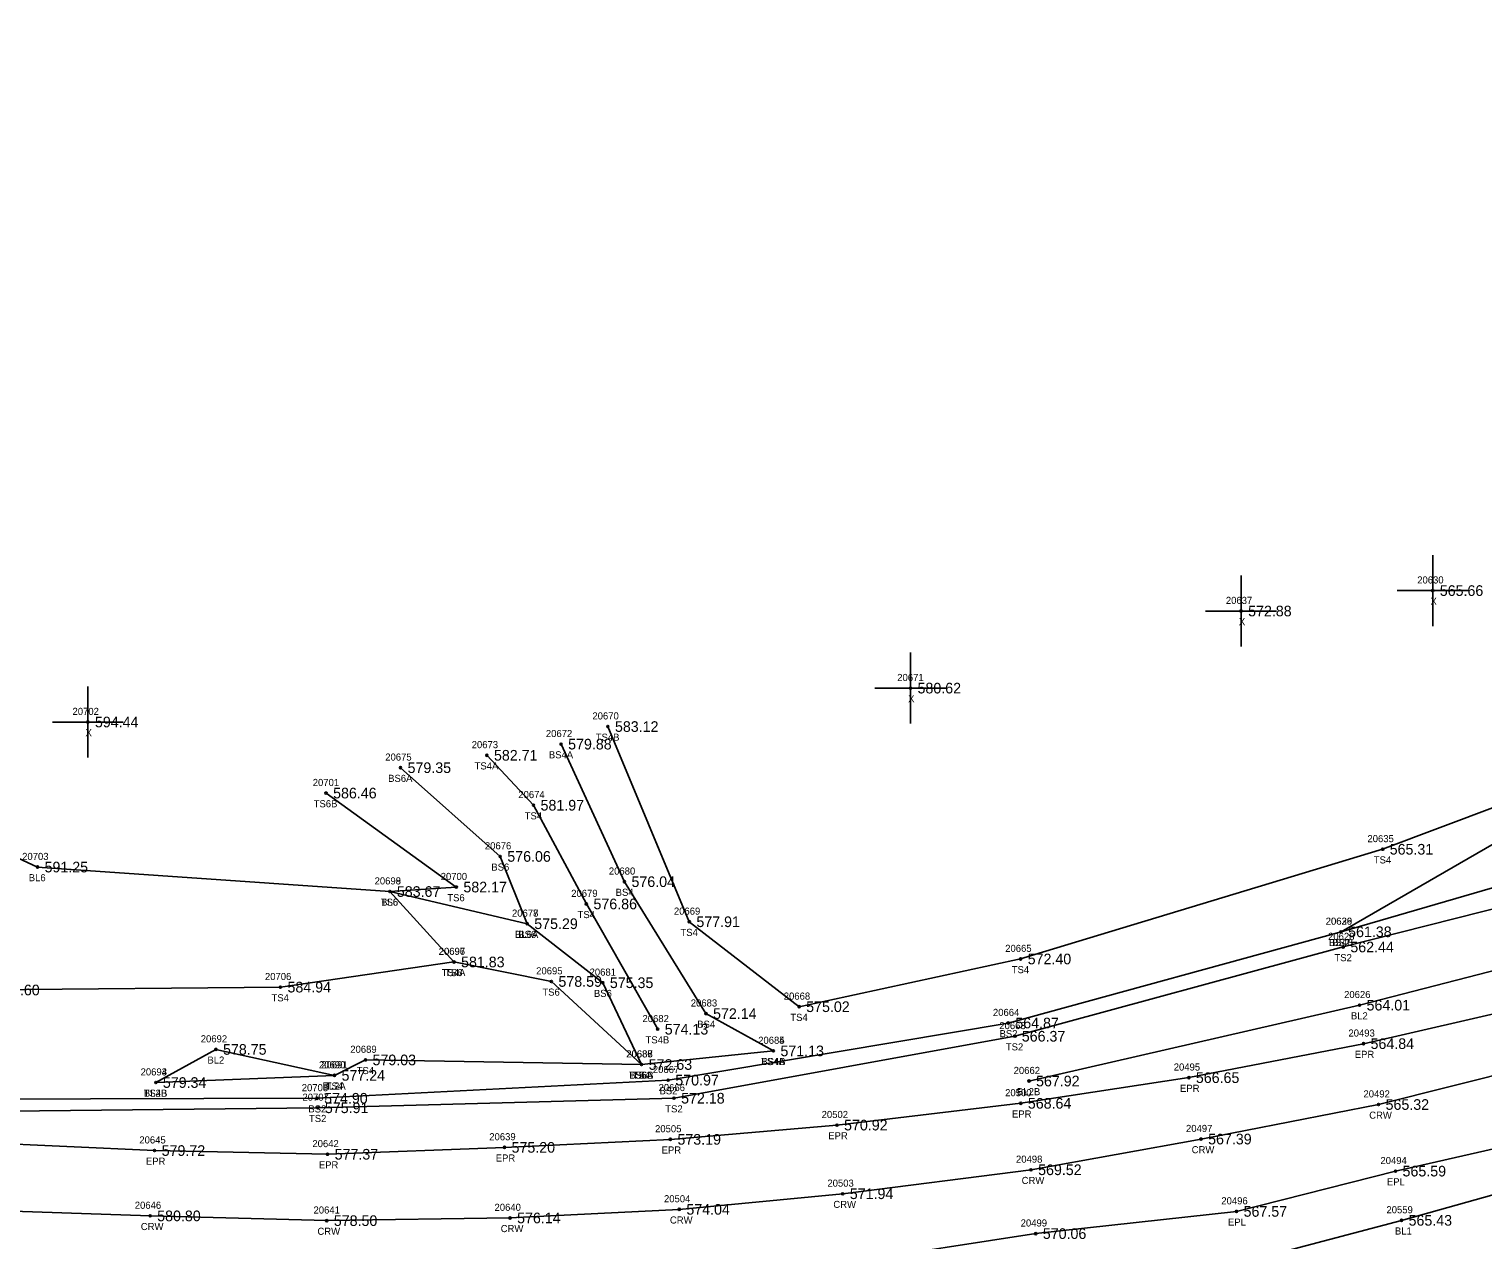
# Model space of a CAD drawing. Extents: x 1540443 to 1541844, y 887157 to 888162.
# Drawn here: x 1540572.9 to 1540777.9, y 887551.3 to 887722 of the extents above; entities that cross this region are included whole.
import ezdxf

# ---------------------------------------------------------------- set-up
doc = ezdxf.new("R2010")
doc.units = 0
for name, color, linetype in [('RD_DTM_BkLn1', 7, 'Continuous'), ('RD_DTM_BkLn2', 7, 'Continuous'), ('RD_DTM_BkLn_txCode', 7, 'Continuous'), ('RD_EX_Misc', 7, 'Continuous'), ('RD_EX_Misc_txCode', 7, 'Continuous'), ('RD_EX_Road', 7, 'Continuous'), ('RD_EX_Road_txCode', 7, 'Continuous'), ('RD_EX_TX_Misc_ELEV', 7, 'Continuous'), ('RD_EX_TX_Road_ELEV', 7, 'Continuous'), ('RD_HC_Survey_ELEV', 7, 'Continuous'), ('RD_HC_Survey_txCode', 7, 'Continuous'), ('RD_SMD_Locator', 7, 'Continuous')]:
    doc.layers.add(name, color=color, linetype=linetype)

msp = doc.modelspace()

# ---------------------------------------------------------------- linework, layer by layer
at = {"layer": 'RD_DTM_BkLn1'}
for points in [[(1541121.11, 887687.12), (1541102.24, 887681.39), (1541047.23, 887667.07), (1540999.54, 887652.68), (1540951.37, 887639.83), (1540901.44, 887627.14), (1540855.78, 887612.94), (1540807.53, 887596.54), (1540760.49, 887584.4), (1540713.89, 887573.7)], [(1541126.44, 887673.83), (1541099.94, 887665.81), (1541052.06, 887651.29), (1541003.93, 887637.63), (1540955.85, 887623.48), (1540907.97, 887609.13), (1540859.88, 887595.48), (1540836.31, 887588.86), (1540811.54, 887582.34), (1540783.96, 887575.59), (1540763.17, 887570.39), (1540738.15, 887565.52), (1540714.18, 887561.19), (1540687.63, 887557.81), (1540664.59, 887555.61), (1540640.72, 887554.4), (1540614.88, 887554.02), (1540589.98, 887554.69), (1540565.01, 887555.56), (1540543.6, 887557.4), (1540515.55, 887560.7), (1540490.9, 887564.25), (1540466.38, 887568.75)], [(1540643.14, 887595.88), (1540623.77, 887600.42), (1540574.1, 887603.87), (1540547.73, 887616.11)], [(1540954.63, 887607.67), (1540911.91, 887595.52), (1540863.1, 887582.06), (1540814.48, 887567.51), (1540766.41, 887554.06), (1540717.46, 887541.1), (1540667.62, 887534.76)], [(1540615.97, 887574.5), (1540599.26, 887578.16), (1540590.78, 887573.49)]]:
    msp.add_lwpolyline(points, dxfattribs=at)
at = {"layer": 'RD_DTM_BkLn2'}
for points in [[(1540916.4, 887722.02), (1540881.96, 887690.29), (1540835.96, 887661.52), (1540805.74, 887626.62), (1540783.69, 887609.62), (1540757.89, 887594.74)], [(1541125.73, 887711), (1541094.52, 887702.99), (1541086.54, 887695.93), (1541048.87, 887683.66), (1540995.75, 887663.85), (1540948.75, 887649.66), (1540899.3, 887637.78), (1540852.09, 887622.25), (1540804.6, 887608.33), (1540757.89, 887594.74), (1540710.97, 887581.88), (1540663.03, 887573.83), (1540613.52, 887571.27), (1540565.55, 887571.13), (1540516.75, 887576.29), (1540467.77, 887583.94)], [(1541121.11, 887687.12), (1541116.34, 887691.41), (1541100.71, 887685.78), (1541045.17, 887674.13), (1540997.29, 887658.19), (1540949.92, 887645.1), (1540900.33, 887634.17), (1540852.81, 887620.54), (1540805.55, 887604.61), (1540758.2, 887592.6), (1540711.88, 887580.02), (1540663.85, 887571.28), (1540613.62, 887569.93), (1540565.66, 887569.42), (1540516.87, 887574.64), (1540467.8, 887581.76)], [(1540787.05, 887622.79), (1540780, 887612.51), (1540763.75, 887606.38), (1540712.71, 887590.91), (1540681.48, 887584.18), (1540666, 887596.16), (1540654.52, 887623.68)], [(1540647.92, 887621.2), (1540656.85, 887601.81), (1540668.35, 887583.21), (1540677.85, 887577.95)], [(1540637.46, 887619.63), (1540644.03, 887612.59), (1540651.49, 887598.67), (1540661.54, 887581.01)], [(1540625.28, 887617.88), (1540639.34, 887605.37), (1540643.14, 887595.88), (1540653.8, 887587.56), (1540659.27, 887576.03)], [(1540659.27, 887576.03), (1540646.55, 887587.74), (1540632.82, 887590.49), (1540623.77, 887600.42), (1540633.15, 887601.05), (1540614.78, 887614.3)], [(1540632.82, 887590.49), (1540608.35, 887586.94), (1540567.28, 887586.54), (1540523.85, 887592.4), (1540472.43, 887598.18)], [(1540677.85, 887577.95), (1540659.27, 887576.03), (1540620.34, 887576.68), (1540615.97, 887574.5), (1540590.78, 887573.49)]]:
    msp.add_lwpolyline(points, dxfattribs=at)
at = {"layer": 'RD_EX_Misc'}
for p, q in [((1540770.81, 887637.85), (1540770.81, 887647.85)), ((1540743.79, 887634.97), (1540743.79, 887644.97)), ((1540765.81, 887642.85), (1540775.81, 887642.85)), ((1540738.79, 887639.97), (1540748.79, 887639.97)), ((1540697.18, 887624.1), (1540697.18, 887634.1)), ((1540581.2, 887619.32), (1540581.2, 887629.32)), ((1540692.18, 887629.1), (1540702.18, 887629.1)), ((1540576.2, 887624.32), (1540586.2, 887624.32))]:
    msp.add_line(p, q, dxfattribs=at)
at = {"layer": 'RD_EX_Road'}
for points in [[(1541123.73, 887682.83), (1541097.11, 887675.72), (1541048.24, 887661.15), (1541001.64, 887647.51), (1540952.42, 887633.12), (1540904.06, 887618.5), (1540857.24, 887604.78), (1540833.63, 887598.38), (1540808.59, 887591.31), (1540783.7, 887584.16), (1540761.05, 887578.97), (1540736.42, 887574.18), (1540712.73, 887570.56), (1540686.82, 887567.49), (1540663.33, 887565.48), (1540639.94, 887564.35), (1540615, 887563.38), (1540590.61, 887563.9), (1540565.81, 887565.05), (1540541.4, 887567.22), (1540516.92, 887569.69), (1540492.5, 887573.72), (1540467.49, 887577.97)], [(1541128.99, 887664.81), (1541102.04, 887656.79), (1541055.37, 887642.78), (1541004.6, 887628.06), (1540958.93, 887614.62), (1540910.77, 887599.96), (1540863.12, 887586.35), (1540837, 887578.35), (1540814.37, 887572.63), (1540785.6, 887565.57), (1540765.56, 887561), (1540743.15, 887555.32), (1540714.84, 887552.19), (1540688.66, 887548.15), (1540665.15, 887545.04), (1540640.91, 887544.2), (1540614.99, 887544.1), (1540590.77, 887544.52), (1540565.35, 887545.64), (1540542.9, 887547.56), (1540513.68, 887550.75), (1540490.5, 887554.02), (1540464.65, 887559.04)]]:
    msp.add_lwpolyline(points, dxfattribs=at)
at = {"layer": 'RD_SMD_Locator'}
for centre in [(1540770.81, 887642.85), (1540743.79, 887639.97), (1540697.18, 887629.1), (1540581.2, 887624.32), (1540654.52, 887623.68), (1540647.92, 887621.2), (1540637.46, 887619.63), (1540625.28, 887617.88), (1540614.78, 887614.3), (1540644.03, 887612.59), (1540763.75, 887606.38), (1540639.34, 887605.37), (1540574.1, 887603.87), (1540623.77, 887600.42), (1540623.77, 887600.42), (1540633.15, 887601.05), (1540656.85, 887601.81), (1540651.49, 887598.67), (1540666, 887596.16), (1540643.14, 887595.88), (1540643.14, 887595.88), (1540757.89, 887594.74), (1540757.89, 887594.74), (1540758.2, 887592.6), (1540632.82, 887590.49), (1540632.82, 887590.49), (1540712.71, 887590.91), (1540608.35, 887586.94), (1540646.55, 887587.74), (1540653.8, 887587.56), (1540681.48, 887584.18), (1540760.49, 887584.4), (1540668.35, 887583.21), (1540710.97, 887581.88), (1540661.54, 887581.01), (1540711.88, 887580.02), (1540599.26, 887578.16), (1540677.85, 887577.95), (1540677.85, 887577.95), (1540761.05, 887578.97), (1540620.34, 887576.68), (1540659.27, 887576.03), (1540659.27, 887576.03), (1540659.27, 887576.03), (1540615.97, 887574.5), (1540615.97, 887574.5), (1540663.03, 887573.83), (1540713.89, 887573.7), (1540736.42, 887574.18), (1540590.78, 887573.49), (1540590.78, 887573.49), (1540613.52, 887571.27), (1540613.62, 887569.93), (1540663.85, 887571.28), (1540712.73, 887570.56), (1540763.17, 887570.39), (1540686.82, 887567.49), (1540663.33, 887565.48), (1540738.15, 887565.52), (1540590.61, 887563.9), (1540615, 887563.38), (1540639.94, 887564.35), (1540714.18, 887561.19), (1540765.56, 887561), (1540687.63, 887557.81), (1540664.59, 887555.61), (1540743.15, 887555.32), (1540589.98, 887554.69), (1540614.88, 887554.02), (1540640.72, 887554.4), (1540766.41, 887554.06), (1540714.84, 887552.19)]:
    msp.add_circle(centre, 0.15, dxfattribs=at)

# ---------------------------------------------------------------- texts
at = {"layer": 'RD_DTM_BkLn_txCode'}
for s, p in [('20670', (1540652.34, 887624.68)), ('20672', (1540645.78, 887622.2)), ('20673', (1540635.32, 887620.63)), ('TS4B', (1540652.81, 887621.68)), ('20675', (1540623.13, 887618.88)), ('BS4A', (1540646.2, 887619.2)), ('BS6A', (1540623.54, 887615.88)), ('TS4A', (1540635.73, 887617.63)), ('20701', (1540612.91, 887615.3)), ('TS6B', (1540613.04, 887612.3)), ('20674', (1540641.89, 887613.59)), ('TS4', (1540642.79, 887610.59)), ('20676', (1540637.18, 887606.37)), ('20635', (1540761.61, 887607.38)), ('20703', (1540571.94, 887604.87)), ('TS4', (1540762.51, 887604.38)), ('BL6', (1540572.87, 887601.87)), ('20698', (1540621.63, 887601.42)), ('20699', (1540621.63, 887601.42)), ('20700', (1540630.95, 887602.05)), ('BS6', (1540638.09, 887603.37)), ('20680', (1540654.66, 887602.81)), ('20679', (1540649.35, 887599.67)), ('BS4', (1540655.62, 887599.81)), ('TS6', (1540622.51, 887598.42)), ('BL6', (1540622.55, 887598.42)), ('TS6', (1540631.88, 887599.05)), ('20677', (1540641, 887596.88)), ('20678', (1540641, 887596.88)), ('TS4', (1540650.25, 887596.67)), ('20669', (1540663.83, 887597.16)), ('20636', (1540755.72, 887595.74)), ('20629', (1540755.74, 887595.74)), ('BL6A', (1540641.43, 887593.88)), ('BS6', (1540641.89, 887593.88)), ('TS4', (1540664.75, 887594.16)), ('20628', (1540756.06, 887593.6)), ('20696', (1540630.66, 887591.49)), ('20697', (1540630.68, 887591.49)), ('20665', (1540710.54, 887591.91)), ('BS4B', (1540756.19, 887592.74)), ('BS2', (1540756.66, 887592.74)), ('TS2', (1540756.96, 887590.6)), ('20706', (1540606.17, 887587.94)), ('TS4A', (1540631.09, 887588.49)), ('TS6', (1540631.56, 887588.49)), ('20695', (1540644.41, 887588.74)), ('20681', (1540651.94, 887588.56)), ('TS4', (1540711.46, 887588.91)), ('TS6', (1540645.29, 887585.74)), ('BS6', (1540652.55, 887585.56)), ('20668', (1540679.32, 887585.18)), ('20626', (1540758.32, 887585.4)), ('TS4', (1540607.1, 887584.94)), ('20683', (1540666.21, 887584.21)), ('20682', (1540659.4, 887582.01)), ('BS4', (1540667.12, 887581.21)), ('TS4', (1540680.24, 887582.18)), ('20664', (1540708.81, 887582.88)), ('20663', (1540709.71, 887581.02)), ('BL2', (1540759.28, 887582.4)), ('20692', (1540597.12, 887579.16)), ('TS4B', (1540659.83, 887579.01)), ('20684', (1540675.71, 887578.95)), ('20685', (1540675.71, 887578.95)), ('BS2', (1540709.74, 887579.88)), ('20689', (1540618.2, 887577.68)), ('20686', (1540657.1, 887577.03)), ('20687', (1540657.13, 887577.03)), ('20688', (1540657.13, 887577.03)), ('TS2', (1540710.63, 887578.02)), ('BL2', (1540598.06, 887576.16)), ('20690', (1540613.79, 887575.5)), ('20691', (1540614.11, 887575.5)), ('20667', (1540660.86, 887574.83)), ('TS4A', (1540676.12, 887575.95)), ('BS4B', (1540676.15, 887575.95)), ('20693', (1540588.64, 887574.49)), ('20694', (1540588.64, 887574.49)), ('TS4', (1540619.1, 887574.68)), ('TS6A', (1540657.51, 887574.03)), ('BS6B', (1540657.54, 887574.03)), ('TS4', (1540658.02, 887574.03)), ('20662', (1540711.73, 887574.7)), ('TS4B', (1540589.07, 887571.49)), ('BL2B', (1540589.1, 887571.49)), ('20708', (1540611.36, 887572.27)), ('20707', (1540611.46, 887570.93)), ('BL2A', (1540614.28, 887572.5)), ('TS4', (1540614.73, 887572.5)), ('20666', (1540661.67, 887572.28)), ('BS2', (1540661.8, 887571.83)), ('BL2B', (1540712.21, 887571.7)), ('BS2', (1540612.29, 887569.27)), ('TS2', (1540662.61, 887569.28)), ('TS2', (1540612.38, 887567.93)), ('20559', (1540764.29, 887555.06)), ('BL1', (1540765.49, 887552.06))]:
    msp.add_text(s, height=1, dxfattribs=at).set_placement(p)
at = {"layer": 'RD_EX_Misc_txCode'}
for s, p in [('20630', (1540768.63, 887643.85)), ('20637', (1540741.65, 887640.97)), ('X', (1540770.5, 887640.85)), ('X', (1540743.48, 887637.97)), ('20671', (1540695.32, 887630.1)), ('X', (1540696.86, 887627.1)), ('20702', (1540579.04, 887625.32)), ('X', (1540580.88, 887622.32))]:
    msp.add_text(s, height=1, dxfattribs=at).set_placement(p)
at = {"layer": 'RD_EX_Road_txCode'}
for s, p in [('20493', (1540758.93, 887579.97)), ('EPR', (1540759.82, 887576.97)), ('20495', (1540734.3, 887575.18)), ('20500', (1540710.53, 887571.56)), ('EPR', (1540735.19, 887572.18)), ('20502', (1540684.66, 887568.49)), ('EPR', (1540711.5, 887568.56)), ('20645', (1540588.46, 887564.9)), ('20639', (1540637.8, 887565.35)), ('20505', (1540661.17, 887566.48)), ('EPR', (1540685.59, 887565.49)), ('20642', (1540612.86, 887564.38)), ('EPR', (1540662.1, 887563.48)), ('EPR', (1540589.38, 887561.9)), ('EPR', (1540613.77, 887561.38)), ('EPR', (1540638.71, 887562.35)), ('20494', (1540763.44, 887562)), ('EPL', (1540764.35, 887559)), ('20496', (1540741.01, 887556.32)), ('20499', (1540712.72, 887553.19)), ('EPL', (1540741.95, 887553.32))]:
    msp.add_text(s, height=1, dxfattribs=at).set_placement(p)
at = {"layer": 'RD_EX_TX_Misc_ELEV'}
for s, p in [('565.66', (1540771.81, 887642.1)), ('572.88', (1540744.79, 887639.22)), ('580.62', (1540698.18, 887628.35)), ('594.44', (1540582.2, 887623.57)), ('583.12', (1540655.52, 887622.93)), ('579.88', (1540648.92, 887620.45)), ('582.71', (1540638.46, 887618.88)), ('579.35', (1540626.28, 887617.13)), ('586.46', (1540615.78, 887613.55)), ('581.97', (1540645.03, 887611.84)), ('565.31', (1540764.75, 887605.63)), ('591.25', (1540575.1, 887603.12)), ('576.06', (1540640.34, 887604.62)), ('576.04', (1540657.85, 887601.06)), ('583.67', (1540624.77, 887599.67)), ('583.67', (1540624.77, 887599.67)), ('582.17', (1540634.15, 887600.3)), ('576.86', (1540652.49, 887597.92)), ('575.29', (1540644.14, 887595.13)), ('575.29', (1540644.14, 887595.13)), ('577.91', (1540667, 887595.41)), ('561.38', (1540758.89, 887593.99)), ('561.38', (1540758.89, 887593.99)), ('562.44', (1540759.2, 887591.85)), ('581.83', (1540633.82, 887589.74)), ('581.83', (1540633.82, 887589.74)), ('572.40', (1540713.71, 887590.16)), ('578.59', (1540647.55, 887586.99)), ('575.35', (1540654.8, 887586.81)), ('594.60', (1540568.28, 887585.79)), ('584.94', (1540609.35, 887586.19)), ('572.14', (1540669.35, 887582.46)), ('575.02', (1540682.48, 887583.43)), ('564.01', (1540761.49, 887583.65)), ('564.87', (1540711.97, 887581.13)), ('574.13', (1540662.54, 887580.26)), ('566.37', (1540712.88, 887579.27)), ('578.75', (1540600.26, 887577.41)), ('571.13', (1540678.85, 887577.2)), ('571.13', (1540678.85, 887577.2)), ('579.03', (1540621.34, 887575.93)), ('572.63', (1540660.27, 887575.28)), ('572.63', (1540660.27, 887575.28)), ('572.63', (1540660.27, 887575.28)), ('579.34', (1540591.78, 887572.74)), ('579.34', (1540591.78, 887572.74)), ('577.24', (1540616.97, 887573.75)), ('577.24', (1540616.97, 887573.75)), ('570.97', (1540664.03, 887573.08)), ('567.92', (1540714.89, 887572.95)), ('574.90', (1540614.52, 887570.52)), ('572.18', (1540664.85, 887570.53)), ('575.91', (1540614.62, 887569.18)), ('565.43', (1540767.41, 887553.31))]:
    msp.add_text(s, height=1.5, dxfattribs=at).set_placement(p)
at = {"layer": 'RD_EX_TX_Road_ELEV'}
for s, p in [('564.84', (1540762.05, 887578.22)), ('566.65', (1540737.42, 887573.43)), ('568.64', (1540713.73, 887569.81)), ('570.92', (1540687.82, 887566.74)), ('573.19', (1540664.33, 887564.73)), ('579.72', (1540591.61, 887563.15)), ('577.37', (1540616, 887562.63)), ('575.20', (1540640.94, 887563.6)), ('565.59', (1540766.56, 887560.25)), ('567.57', (1540744.15, 887554.57)), ('570.06', (1540715.84, 887551.44))]:
    msp.add_text(s, height=1.5, dxfattribs=at).set_placement(p)
at = {"layer": 'RD_HC_Survey_ELEV'}
for s, p in [('565.32', (1540764.17, 887569.64)), ('567.39', (1540739.15, 887564.77)), ('569.52', (1540715.18, 887560.44)), ('571.94', (1540688.63, 887557.06)), ('580.80', (1540590.98, 887553.94)), ('574.04', (1540665.59, 887554.86)), ('578.50', (1540615.88, 887553.27)), ('576.14', (1540641.72, 887553.65))]:
    msp.add_text(s, height=1.5, dxfattribs=at).set_placement(p)
at = {"layer": 'RD_HC_Survey_txCode'}
for s, p in [('20492', (1540761.05, 887571.39)), ('20497', (1540736.03, 887566.52)), ('CRW', (1540761.86, 887568.39)), ('CRW', (1540736.83, 887563.52)), ('20498', (1540712.06, 887562.19)), ('20503', (1540685.47, 887558.81)), ('CRW', (1540712.86, 887559.19)), ('20504', (1540662.43, 887556.61)), ('20646', (1540587.82, 887555.69)), ('20641', (1540613.02, 887555.02)), ('20640', (1540638.54, 887555.4)), ('CRW', (1540686.31, 887555.81)), ('CRW', (1540588.67, 887552.69)), ('CRW', (1540639.41, 887552.4)), ('CRW', (1540663.27, 887553.61)), ('CRW', (1540613.57, 887552.02))]:
    msp.add_text(s, height=1, dxfattribs=at).set_placement(p)

doc.saveas('drawing.dxf')
